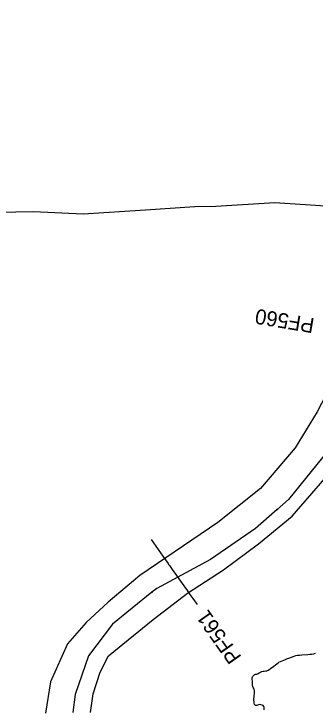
# Model space of a CAD drawing. Extents: x -737422 to -734235, y -1145631 to -1142623.
# Drawn here: x -735291.7 to -735091.9, y -1143271.9 to -1142807.4 of the extents above; entities that cross this region are included whole.
import ezdxf

# ---------------------------------------------------------------- set-up
doc = ezdxf.new("R2010")
doc.units = 0
for name, color, linetype in [('Vrstva 1', 7, 'Continuous'), ('Vrstva 2', 7, 'Continuous'), ('Vrstva 3', 7, 'Continuous'), ('Vrstva 6', 7, 'Continuous'), ('Vrstva 8', 7, 'Continuous'), ('Vrstva 9', 7, 'Continuous')]:
    doc.layers.add(name, color=color, linetype=linetype)

# ---------------------------------------------------------------- blocks, each defined once
blk = doc.blocks.new('1.050')
at = {"layer": 'Vrstva 1'}
for radius in [0.5, 0.001]:
    blk.add_circle((0, 0), radius, dxfattribs=at)

msp = doc.modelspace()

# ---------------------------------------------------------------- linework, layer by layer
at = {"layer": 'Vrstva 1'}
for points in [[(-735132.441, -1143262.331), (-735132.379, -1143261.249), (-735132.259, -1143260.218), (-735132.055, -1143258.886), (-735132.021, -1143258.005), (-735132.104, -1143257.146), (-735132.311, -1143256.353), (-735132.637, -1143255.656), (-735133.004, -1143255.012), (-735133.317, -1143254.363), (-735133.466, -1143253.846), (-735133.535, -1143253.316), (-735133.49, -1143251.472), (-735133.506, -1143250.68), (-735133.601, -1143249.398), (-735133.616, -1143248.9), (-735133.556, -1143248.412), (-735133.409, -1143247.953), (-735133.174, -1143247.543), (-735132.882, -1143247.169), (-735132.559, -1143246.822), (-735132.201, -1143246.526), (-735131.799, -1143246.306), (-735131.376, -1143246.157), (-735130.524, -1143245.969), (-735130.072, -1143245.832), (-735129.62, -1143245.633), (-735129.045, -1143245.271), (-735128.468, -1143244.865), (-735127.839, -1143244.498), (-735127.125, -1143244.238), (-735126.363, -1143244.079), (-735125.607, -1143244.003), (-735124.536, -1143243.948), (-735123.995, -1143243.85), (-735123.461, -1143243.674), (-735122.946, -1143243.418), (-735121.909, -1143242.775), (-735121.385, -1143242.407), (-735119.301, -1143240.708), (-735118.237, -1143239.805), (-735116.502, -1143238.55), (-735115.888, -1143238.161), (-735114.88, -1143237.661), (-735112.701, -1143236.821), (-735111.627, -1143236.383), (-735110.258, -1143235.737), (-735109.304, -1143235.347), (-735105.877, -1143234.07), (-735104.713, -1143233.766), (-735103.462, -1143233.548), (-735102.15, -1143233.39)], [(-735102.15, -1143233.39), (-735100.796, -1143233.272), (-735096.648, -1143232.994), (-735095.288, -1143232.875), (-735093.968, -1143232.718), (-735092.708, -1143232.503), (-735091.534, -1143232.208)], [(-735125.788, -1143269.849), (-735125.727, -1143269.587), (-735125.687, -1143268.851), (-735125.773, -1143268.148), (-735125.99, -1143267.517), (-735126.35, -1143267.003), (-735127.004, -1143266.577), (-735127.799, -1143266.365), (-735128.638, -1143266.333), (-735129.423, -1143266.461), (-735130.536, -1143266.9), (-735131.017, -1143267.003), (-735131.366, -1143266.938), (-735131.68, -1143266.729), (-735132.02, -1143266.178), (-735132.247, -1143265.396), (-735132.383, -1143264.455), (-735132.444, -1143263.416), (-735132.441, -1143262.331)]]:
    msp.add_lwpolyline(points, dxfattribs=at)
at = {"layer": 'Vrstva 2'}
msp.add_lwpolyline([(-735062.19, -1143054.47), (-735067.52, -1143070.46), (-735083.15, -1143097.45), (-735109.45, -1143130.12), (-735117, -1143136.7), (-735131.48, -1143149.3), (-735161.32, -1143169.9), (-735197.01, -1143189.05), (-735200.15, -1143191.6), (-735226.32, -1143212.89), (-735242.32, -1143233.92), (-735251.01, -1143259.51), (-735252.721, -1143271.637)], dxfattribs=at)
at = {"layer": 'Vrstva 3'}
for points in [[(-735034.121, -1142807.443), (-735041.41, -1142833.15), (-735049.67, -1142873.94), (-735063.61, -1142929.72), (-735068.77, -1142951.92), (-735071.87, -1143011.83), (-735079.1, -1143049.53), (-735090.46, -1143071.74), (-735105.06, -1143095.74), (-735128.12, -1143122.71), (-735156.5, -1143145.42), (-735208.29, -1143180.56), (-735229.22, -1143198.3), (-735243.77, -1143211.78), (-735256.18, -1143225.98), (-735267.54, -1143251.18), (-735270.892, -1143271.893)], [(-735241.006, -1143271.472), (-735239.15, -1143259.17), (-735234.58, -1143244.68), (-735228.99, -1143234), (-735199.27, -1143209.85), (-735176.65, -1143192.31), (-735152.77, -1143176.8), (-735129.4, -1143159.51), (-735107.11, -1143141.06), (-735088.31, -1143119.45), (-735077.39, -1143106.74), (-735077.49, -1143105.7), (-735076.93, -1143104.86), (-735076.56, -1143104.21), (-735076.01, -1143103.75), (-735075.46, -1143102.81), (-735072.37, -1143096.66), (-735069.15, -1143092.35)]]:
    msp.add_lwpolyline(points, dxfattribs=at)
at = {"layer": 'Vrstva 8'}
for points in [[(-735314.01, -1142939.28), (-735278.66, -1142938.62), (-735245.76, -1142940.24), (-735204.54, -1142937.66), (-735171.6, -1142935.43), (-735157.76, -1142935.05), (-735118.71, -1142932.59), (-735071.5, -1142935.89)], [(-735200.76, -1143156.56), (-735192.93, -1143167.67), (-735189.42, -1143172.65), (-735189.07, -1143173.14), (-735188.55, -1143173.89), (-735186.67, -1143176.55), (-735183.88, -1143180.51), (-735181.24, -1143184.26), (-735177.87, -1143189.03), (-735177.11, -1143190.1), (-735175.65, -1143192.19), (-735173.12, -1143195.77), (-735170.23, -1143199.87)]]:
    msp.add_lwpolyline(points, dxfattribs=at)

# ---------------------------------------------------------------- block references
at = {"layer": 'Vrstva 6', "xscale": 0.5, "yscale": 0.5}
for p in [(-735117, -1143136.7), (-735200.15, -1143191.6)]:
    msp.add_blockref('1.050', p, dxfattribs=at)

# ---------------------------------------------------------------- texts
at = {"layer": 'Vrstva 9'}
for s, rotation, p in [('PF560', 170.451, (-735091.82, -1143009.75)), ('PF561', 125.179, (-735140.36, -1143234.7))]:
    msp.add_text(s, height=10, rotation=rotation, dxfattribs=at).set_placement(p)

doc.saveas('drawing.dxf')
